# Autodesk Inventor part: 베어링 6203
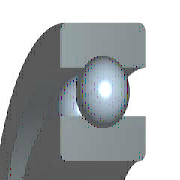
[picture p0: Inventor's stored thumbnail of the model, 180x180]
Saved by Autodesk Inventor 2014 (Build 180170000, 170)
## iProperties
IsCustomPart: 1
Created: 2015-09
Part Number: 베어링 6203
Material: 강철, 연강
Description: 깊은 그루브 볼 베어링
Document SubType Name: Modeling
Standard: KS B 2023
Standards Organization: KS
Language: ko-KR
Size Designation: 6203 - 17 x 40 x 12
Categories: <MemberInstance><Categories><Category DisplayName="샤프트 부품" InternalName="7f7aeb1f-a693-4053-b835-cee3144e0d98" Mnemonic="SHFT"><Category DisplayName="베어링" Inter
Density: 7.86 g/cm^3
Appearance: 강철
Mass: 58.8203 g
Surface Area: 64.3582 cm^2
Volume: 7.4835 cm^3
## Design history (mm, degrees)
sketch "스케치" dims "d0" = 5.98 (= -0.26 x WD + 0.26 x BD)
  geometry: L1 (3.01, 14.25)-(8.99, 14.25); L2 (6, 14.25)-(6, 11.26); L3 (6, 14.25)-(6, 17.24); L4 (3.778, 12.249)-(0, 12.249); L5 (0, 8.5)-(12, 8.5); L6 (3.778, 16.251)-(0, 16.251); L7 (0, 20)-(12, 20); L8 (12, 8.5)-(12, 12.249); L9 (8.222, 12.249)-(12, 12.249); L10 (8.222, 16.251)-(12, 16.251); L11 (12, 20)-(12, 16.251); L12 (-1.4, 0)-(8.4, 0) reference; L13 (0, -0.3)-(0, 5.3) reference
  constraints: 22 end point, 4 point on line, 2 collinear, 2 perpendicular, 2 symmetric about line, 1 midpoint, 1 parallel, 14 other
  dimensions: "d9" = 17 diameter of L5 L12 (= WD); "d11" = 40 diameter of L7 L12 (= BD); "d12" = 12 distance between parallel lines of L8 L13 (= KB); "d13" = 24.498 diameter of L9 L12 (= 0.326 x BD + 0.674 x WD)
revolve "본체" stored, may be unused: angle "d6" = 90 deg
revolve "볼" stored, may be unused: angle "d7" = 90 deg
pattern_circular "IDS_ARRAYBALL[SIMPL:T]" dims angle "d3" = 360 deg
body "Solid1"
fillet "모깎기1" dims "d1" = 0.6 (= KRS)
other parameters: "WD" = 17 [user parameter; used in 5 equation terms], "BD" = 40 [user parameter; used in 5 equation terms], "KB" = 12 [user parameter; used in 1 equation term], "KRS" = 0.6 [user parameter; used in 1 equation term], "d4" = 0, "d5" = 0, "d8" = 0, "d14" = 0, "d15" = 0, "BBA" = 0 [user parameter], "BC0" = 4750000 [user parameter], "BC" = 9560000 [user parameter], "WR" = 8.5 (= 0.5 x WD) [user parameter]
